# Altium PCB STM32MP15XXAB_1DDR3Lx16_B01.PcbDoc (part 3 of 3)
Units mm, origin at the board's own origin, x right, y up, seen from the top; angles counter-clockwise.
Board outline 86 x 120 mm, 4 copper layers (Top Layer, Signal Layer 1, Signal Layer 2, Bottom Layer), stack 1.571 mm thick; 144 components, 93 nets, 930 pads, 372 vias.
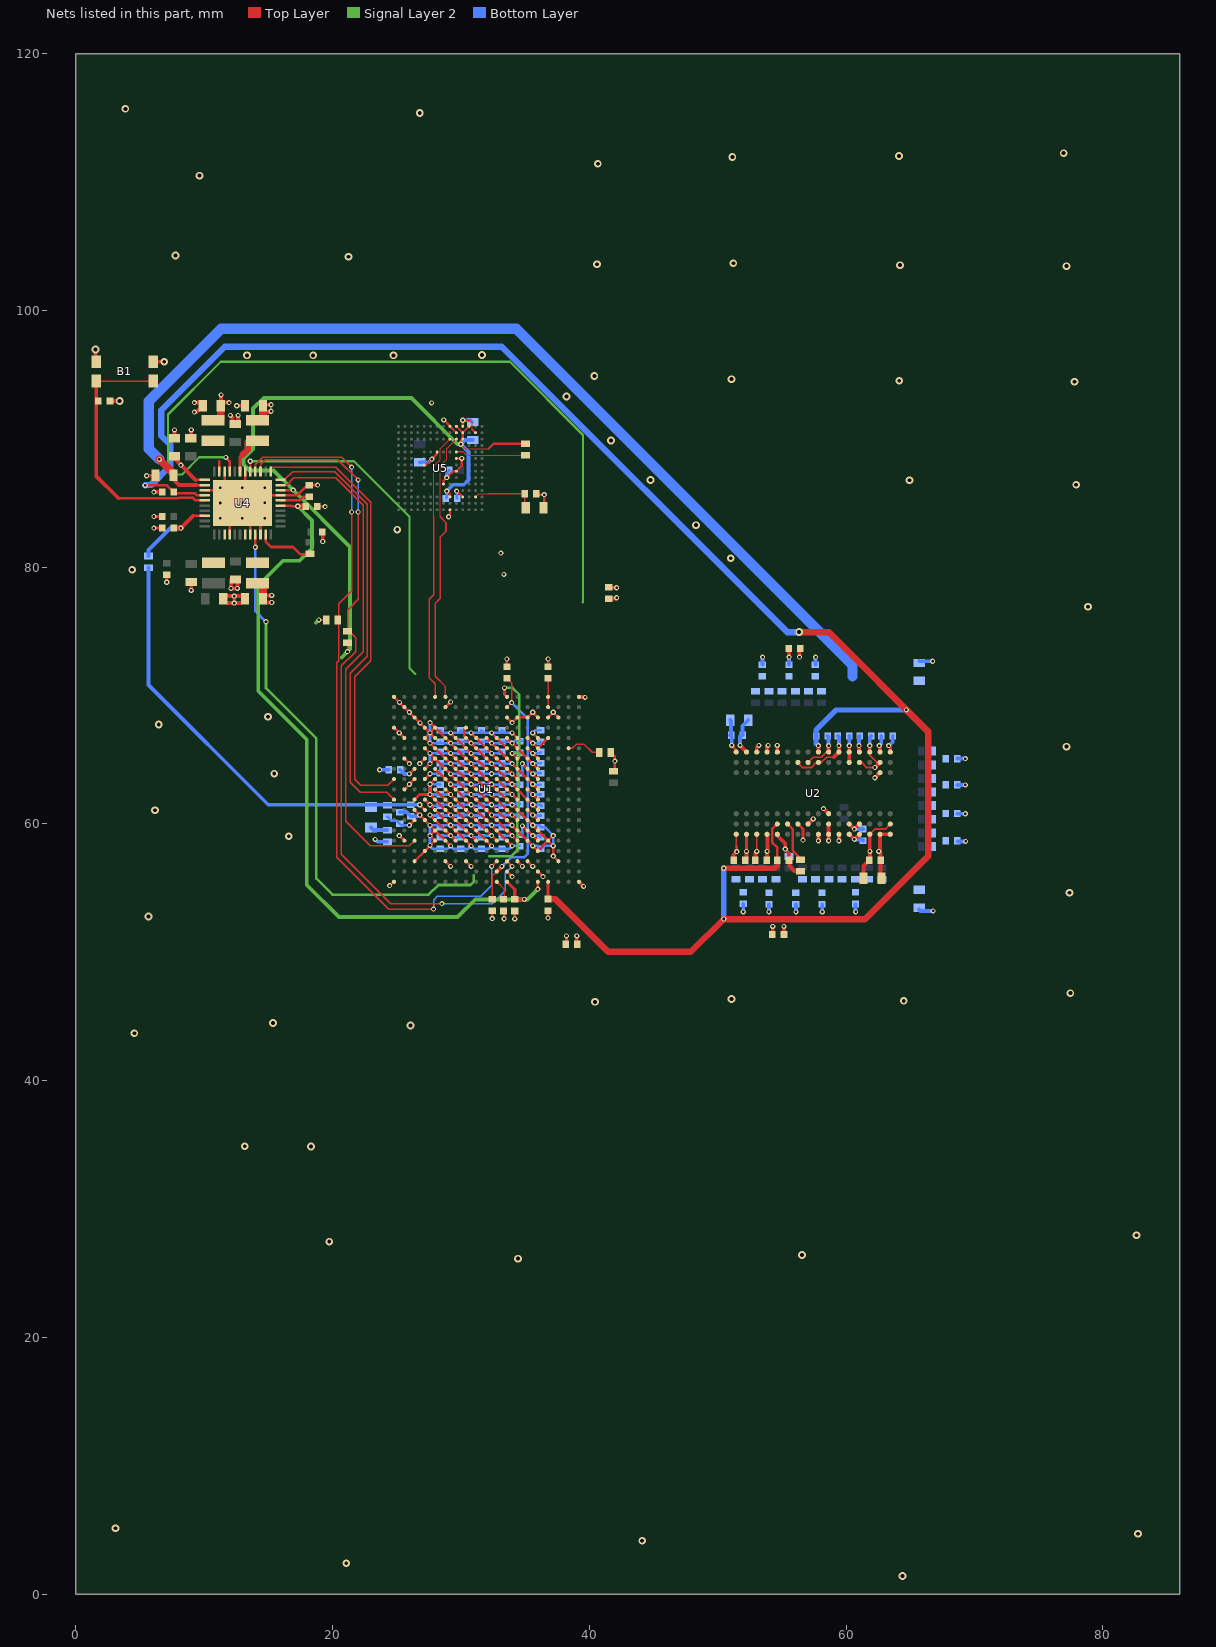
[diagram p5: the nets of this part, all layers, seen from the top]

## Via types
v1: diameter 0.4, hole 0.2, Top Layer to Bottom Layer, tented both sides, 309 vias
v2: diameter 0.6, hole 0.3, Top Layer to Bottom Layer, tented both sides, 61 vias
v3: diameter 0.4, hole 0.2, Top Layer to Signal Layer 1, tented top, 2 vias

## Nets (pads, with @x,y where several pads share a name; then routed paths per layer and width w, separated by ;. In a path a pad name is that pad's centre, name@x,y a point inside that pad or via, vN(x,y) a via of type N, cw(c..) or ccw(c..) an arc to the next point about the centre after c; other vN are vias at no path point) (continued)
GND: B1.1 B1.2 C1.1 C2.1 C3.1 C4.1 C5.1 C6.1 C7.1 C8.1 C9.1 C10.1 C11.1 C12.1 C13.1 C14.1 C15.1 C16.1 C17.1 C18.1 C19.1 C20.1 C21.1 C22.2 C23.1 C24.1 C25.1 C26.1 C27.1 C28.1 C29.1 C30.1 C31.1 C32.1 C33.1 C34.1 C35.1 C36.1 C37.1 C38.1 C39.1 C40.1 C41.1 C42.1 C43.1 C44.1 C45.1 C46.1 C47.1 C48.1 C49.1 C50.1 C51.2 C52.1 C53.1 C54.1 C55.1 C56.1 C57.1 C58.1 C59.1 C60.1 C61.1 C62.1 C63.1 C64.1 C65.1 C66.1 C67.1 C68.1 C69.1 C70.1 C71.1 C72.1 C73.1 C74.1 C75.1 C76.1 C77.1 C78.1 C79.1 C80.1 C81.1 C82.1 C83.1 C84.1 C85.1 C86.1 C87.1 C88.1 C89.1 C90.1 C91.1 C92.1 C93.1 C94.1 C95.1 C96.1 C97.1 R26.1 R27.2 R29.1 R30.1 U1.A1 U1.A19 U1.B2 U1.B6 U1.C3 U1.C12 U1.C13 U1.C14 U1.C15 U1.C16 U1.C17 U1.D1 U1.D4 U1.D5 U1.D8 U1.E2 U1.E4 U1.E5 U1.E6 U1.E8 U1.E10 U1.E12 U1.E14 U1.E16 U1.F5 U1.F7 U1.F9 U1.F11 U1.F13 U1.F15 U1.G2 U1.G4 U1.G6 U1.G8 U1.G10 U1.G12 U1.G14 U1.H5 U1.H7 U1.H9 U1.H11 U1.H13 U1.H15 U1.J3 U1.J4 U1.J6 U1.J8 U1.J10 U1.J12 U1.J14 U1.K2 U1.K5 U1.K7 U1.K9 U1.K11 U1.K13 U1.K15 U1.L4 U1.L6 U1.L8 U1.L10 U1.L12 U1.L14 U1.M3 U1.M5 U1.M7 U1.M9 U1.M11 U1.M13 U1.M15 U1.N4 U1.N6 U1.N8 U1.N10 U1.N12 U1.N14 U1.P5 U1.P7 U1.P9 U1.P11 U1.P13 U1.P15 U1.R2 U1.R5 U1.R6 U1.R8 U1.R10 U1.R12 U1.R14 U1.R16 U1.T4 U1.T15 U1.U3 U1.U6 U1.U8 U1.U13 U1.U14 U1.U17 U1.V12 U1.V15 U1.W1 U1.W19 U2.A9 U2.B1 U2.B3 U2.B9 U2.D1 U2.D8 U2.E1 U2.E2 U2.E8 U2.F9 U2.G1 U2.G8 U2.G9 U2.J2 U2.J8 U2.M1 U2.M9 U2.P1 U2.P9 U2.T1 U2.T9 U4.6 U4.10 U4.15 U4.26 U4.30 U4.32 U4.41 U4.ep U5.A6 U5.C4 U5.E7 U5.G5 U5.H10 U5.J5 U5.K8 U5.N2 U5.N5 U5.P4 U5.P6 | length 253.9
  Top Layer w0.09: 30.675,91.45 30.9,91.225 30.9,90.725
  Top Layer w0.12: U1.U17@37.55,57.1 U1.U17@37.6,57.1 ; U2.M1@54.65,65.6 U2.M1@54.65,65.7 ; C25.1@55.54,57.19 C25.1@55.56,57.17 ; v1@58.65,58.61 v1(58.65,58.7) ; U2.E8@60.25,60 U2.E8@60.27,60
  Top Layer w0.15: 51.45,58.25 U2.T9@51.45,59.2 ; v1(53.05,57.87) U2.P9@53.05,59.2 ; U2.J2@57.05,64.8 57.45,65.2 58.07,65.2 58.47,65.6 U2.G1@58.65,65.6
  Top Layer w0.175: B1.1@1.55,96.05 B1.1@1.6,96 B1.1@1.6,96.25 ; C46.1@6.2,87.125 C46.1@6.225,87.15 ; C18.1@8.975,90.05 C18.1@9,90.075 ; C29.1@9.65,92.825 C29.1@9.9,92.575 ; C40.1@11.7,77.75 C40.1@11.5,77.55 11.85,77.2 ; C33.1@12.425,91.15 C33.1@12.65,91.375 ; 12.85,77.2 C38.1@13.2,77.55 C38.1@13,77.75 ; U4.ep@13,85 13.2,85.2 13.6,85.6 U4.41@15.95,85.6 ; C52.1@18.85,84.725 v1(19.425,84.725) ; C51.2@19.2,82.75 C51.2@19.25,82.7 ; U5.H10@27.15,87.975 27.3,87.975 v1(27.75,88.425) 28.15,88.825 U5.K8@28.15,88.975 ; U5.E7@28.65,86.475 28.65,86.725 v1(28.9,86.975) 29.4,87.475 U5.G5@29.65,87.475 30.075,87.9 v1(30.075,88.475) U5.J5@29.65,88.475 ; v1(28.675,91.475) 29.15,91 U5.P6@29.15,90.975 U5.N5@29.65,90.475 ; v1(29.05,83.925) 29.15,84.025 U5.A6@29.15,84.475 ; v1(29.675,85.925) 29.7,85.925 U5.C4@30.15,85.475 ; U5.P4@30.15,90.948 U5.P4@30.15,90.975 v1(30.15,91.45) 30.675,91.45 ; 30.9,90.725 U5.N2@31.15,90.475 ; v1@33.125,81 v1(33.125,81.1) ; C82.1@35.875,85.725 35.95,85.65 v1(36.5,85.65) 36.5,84.675 C83.1@36.45,84.625
  Top Layer w0.2: U4.15@10.05,86 U4.ep@12,86 ; U4.10@11.6,87.45 11.6,86.4 U4.ep@12,86 ; U4.26@12,82.55 12,84 U4.ep@13,85 ; U4.ep@13.2,85.2 U4.6@13.2,87.45 ; U4.30@13.6,82.55 U4.ep@13.6,84.4 ; U4.32@14.4,82.55 14.4,83.6 U4.ep@13.6,84.4 ; U4.41@15.95,85.6 17.25,85.6 18.05,86.4 C43.1@18.2,86.4 ; v1(24.45,55.2) 24.75,55.5 U1.W1@24.8,55.5 ; U1.D1@24.8,67.5 U1.E2@25.6,66.7 ; U1.A1@24.8,69.9 v1(25.225,69.475) v1(26,68.7) v1(27.6,67.1) ; v1(25.2,59.1) U1.R2@25.6,58.7 ; U1.K2@25.6,62.7 v1(26,63.1) U1.J3@26.4,63.5 ; U1.G2@25.6,65.1 v1(26,64.7) ; U1.U3@26.4,57.1 U1.T4@27.2,57.9 U1.R5@28,58.7 v1(27.6,59.1) U1.P5@27.995,59.495 ; U1.M3@26.4,61.1 v1(26.8,60.7) U1.N4@27.2,60.3 27.2,60.29 v1(27.6,59.89) U1.P5@27.995,59.495 ; v1(26.8,64.7) U1.G4@27.2,65.1 ; U1.L4@27.2,61.9 v1(27.6,61.5) v1(29.2,59.9) U1.R8@30.4,58.7 v1(30.8,58.3) ; U1.J4@27.2,63.5 27.2,63.51 v1(27.6,63.91) ; v1(27.6,67.9) U1.D5@28,67.5 ; U1.P5@28,59.5 U1.P5@27.995,59.495 ; U1.K5@28,62.7 v1(29.2,61.5) U1.M7@29.6,61.1 U1.P9@31.2,59.5 U1.R10@32,58.7 v1(32.4,58.3) ; U1.H5@28,64.3 U1.J6@28.8,63.5 v1(29.2,63.1) v1(30.8,61.5) U1.M9@31.2,61.1 U1.N10@32,60.3 v1(32.4,59.9) v1(34,58.3) ; U1.E5@28,66.7 v1(27.6,67.1) ; U1.U6@28.8,57.1 v1(29.2,56.7) ; U1.B6@28.8,69.1 v1(29.2,69.5) ; v1(29.2,58.3) U1.R6@28.8,58.7 28.79,58.7 U1.P5@27.995,59.495 ; U1.U8@30.4,57.1 v1(30.8,56.7) ; U1.D8@30.4,67.5 30.27,67.37 30.27,66.83 U1.E8@30.4,66.7 v1(30.8,66.3) U1.G10@32,65.1 v1(32.4,64.7) v1(34,63.1) v1(35.6,61.5) U1.M15@36,61.1 ; U1.E10@32,66.7 v1(32.4,66.3) v1(34,64.7) U1.H13@34.4,64.3 v1(35.6,63.1) U1.K15@36,62.7 ; v1(32.45,52.63) C67.1@32.45,53.24 ; v1(33.37,52.62) C69.1@33.37,53.24 ; C66.1@33.59,72.37 v1@33.59,72.84 ; U1.V12@33.6,56.3 v1(34,55.9) ; U1.E12@33.6,66.7 v1(34,66.3) U1.G14@35.2,65.1 v1(35.6,64.7) U1.H15@36,64.3 ; U1.C12@33.6,68.3 v1(34,67.9) U1.C13@34.4,68.3 U1.C14@35.2,68.3 v1(35.6,68.7) U1.C15@36,68.3 ; v1(34.2,52.605) C71.1@34.2,53.225 ; U1.U13@34.4,57.1 v1(34.8,56.7) ; U1.U14@35.2,57.1 v1(35.6,56.7) ; U1.E14@35.2,66.7 v1(35.6,66.3) U1.F15@36,65.9 U1.E16@36.8,66.7 ; U1.V15@36,56.3 v1(36.4,55.9) ; v1(36.79,52.68) C72.1@36.79,53.26 ; U1.C16@36.8,68.3 v1(37.2,68.7) U1.C17@37.6,68.3 ; C68.1@36.8,72.25 v1(36.8,72.85) ; v1(37.2,59.1) U1.R16@36.8,58.7 ; U1.U17@37.6,57.1 v1(37.2,57.5) v1(37.2,58.3) U1.R16@36.8,58.7 ; C28.1@38.18,50.63 38.23,50.68 v1(38.23,51.28) ; R27.2@41.73,65.64 R27.2@41.67,65.58 42,65.25 v1(42,64.9) 42,64.225 R29.1@41.875,64.1 ; v1(51.1,66.12) 51.45,65.77 U2.T1@51.45,65.6 ; 51.45,58.25 51.49,58.21 v1(51.49,57.85) ; U4.ep@12,86 U4.ep@13,85 ; U4.ep@13,85 U4.ep@13.6,84.4 ; v1(27.6,67.1) U1.E4@27.2,66.7 v1(27.6,66.3) U1.F5@28,65.9 v1(29.2,64.7) U1.H7@29.6,64.3 U1.J8@30.4,63.5 v1(30.8,63.1) U1.L10@32,61.9 v1(32.4,61.5) U1.M11@32.8,61.1 v1(34,59.9) U1.R14@35.2,58.7 v1(35.6,58.3) U1.T15@36,57.9 U1.R16@36.8,58.7 ; v1(27.6,67.1) U1.D5@28,67.5 ; U1.D5@28,67.5 U1.E6@28.8,66.7 v1(29.2,66.3) U1.G8@30.4,65.1 v1(30.8,64.7) v1(32.4,63.1) U1.K11@32.8,62.7 v1(34,61.5) U1.N14@35.2,60.3 U1.P15@36,59.5 U1.R16@36.8,58.7
  Top Layer w0.25: v3(6.1,83.05) C49.1@6.75,83.05 ; v3(6.1,83.95) C41.1@6.75,83.95 ; v1(7.1,78.825) C32.1@7.1,79.4 ; v1(9,78.2) C39.1@9,78.85 ; C43.1@18.2,86.4 v1(18.85,86.4)
  Top Layer w0.3: B1.1@1.55,96.05 v2(1.55,96.95) ; C44.1@2.675,92.95 v2(3.425,92.95) ; v1(5.525,87.125) C46.1@6.2,87.125 ; B1.2@6.05,96 v2(6.9,96) ; v1(6.1,85.85) C45.1@6.75,85.85 ; C42.1@7.7,90.05 v1(7.7,90.7) ; C18.1@9,90.075 v1(9,90.7) ; v1(9.25,92.075) 9.4,92.075 C29.1@9.9,92.575 ; v1(9.25,92.825) C29.1@9.65,92.825 ; C40.1@11.7,77.75 v1(12.35,77.75) ; 11.85,77.2 v1(12.35,77.2) ; v1(12.05,91.825) 12.225,91.65 C33.1@12.225,91.375 ; C31.1@12.1,79 v1(12.1,78.35) v1(12.6,78.35) 12.6,78.9 C31.1@12.45,79.05 ; v1(12.55,92.575) C34.1@13.2,92.575 ; C33.1@12.65,91.375 v1(12.65,91.825) ; 12.85,77.2 v1(12.35,77.2) ; C38.1@13,77.75 v1(12.35,77.75) ; v1(19.25,82) C51.2@19.25,82.7 ; U1.W19@39.2,55.5 v1(39.56,55.14) ; U1.A19@39.2,69.9 39.64,69.9 v1(39.68,69.86) ; C26.1@41.52,78.45 41.57,78.4 v1(42.13,78.4) ; C73.1@51.25,57.17 51.25,57.61 v1(51.49,57.85) ; C19.1@52.94,57.17 52.94,57.76 v1(53.05,57.87) ; U2.P1@53.05,65.6 53.05,65.96 v1(53.21,66.12) ; U2.M9@54.65,59.2 54.65,59.1 55.27,58.48 v1(55.27,58.05) 55.27,58 55.54,57.73 C25.1@55.54,57.19 ; U2.M1@54.65,65.6 v1(54.65,66.12) ; v1(55.16,52.02) 55.16,51.41 C74.1@55.17,51.4 ; C27.1@55.53,73.68 55.57,73.64 v1(55.57,73) ; C25.1@55.56,57.17 55.59,57.14 55.59,56.72 55.98,56.33 R26.1@56.46,56.33 ; U2.J8@57.05,60 v1(57.45,60.4) ; v1(58.65,58.7) U2.G8@58.65,60 ; U2.G1@58.65,65.6 v1(58.65,66.1) ; v1(59.45,58.7) U2.F9@59.45,59.2 ; U2.E8@60.25,60 v1(60.65,59.6) U2.D8@61.05,60 ; U2.E2@60.25,64.8 v1(60.25,66.1) ; v1(61.01,66.1) 61.01,65.64 U2.D1@61.05,65.6 ; v1(62.25,63.6) U2.B3@62.65,64 ; v1(62.59,66.1) 62.65,66.04 U2.B1@62.65,65.6 ; C15.1@62.7,55.89 C17.1@62.7,57.17 62.7,57.72 v1(62.55,57.87) 62.65,57.97 U2.B9@62.65,59.2 U2.A9@63.45,59.2 ; v1(12.35,77.2) v1(12.35,77.75)
  Bottom Layer w0.12: v1@58.62,66.13 v1(58.65,66.1)
  Bottom Layer w0.175: v1(29.675,85.925) 29.675,85.4 C80.1@29.725,85.35 ; C81.1@30.775,91.45 C81.1@30.925,91.3
  Bottom Layer w0.2: v1(27.6,61.5) 27.68,61.42 C65.1@28.4,61.42 28.48,61.5 v1(29.2,61.5) 29.28,61.42 C88.1@30,61.42 30.08,61.5 v1(30.8,61.5) 30.88,61.42 C89.1@31.6,61.42 31.68,61.5 v1(32.4,61.5) 32.48,61.42 C90.1@33.2,61.42 33.28,61.5 v1(34,61.5) 34.06,61.56 C91.1@34.6,61.56 ; v1(27.6,63.91) 28.34,63.91 C48.1@28.4,63.97 C84.1@28.4,64.72 28.42,64.7 v1(29.2,64.7) 29.22,64.72 C35.1@30,64.72 30.02,64.7 v1(30.8,64.7) 30.82,64.72 C36.1@31.6,64.72 31.62,64.7 v1(32.4,64.7) 32.42,64.72 C37.1@33.2,64.72 33.22,64.7 v1(34,64.7) ; v1(27.6,67.9) v1(27.6,67.1) v1(27.6,66.3) 28.31,66.3 C30.1@28.4,66.39 28.49,66.3 v1(29.2,66.3) 29.91,66.3 C75.1@30,66.39 30.71,66.39 v1(30.8,66.3) 31.51,66.3 C76.1@31.6,66.39 32.31,66.39 v1(32.4,66.3) 33.11,66.3 C77.1@33.2,66.39 33.91,66.39 v1(34,66.3) 34.2,66.5 C47.1@34.8,66.5 ; v1(29.2,63.1) 29.23,63.07 C85.1@30,63.07 30.03,63.1 v1(30.8,63.1) 30.83,63.07 C86.1@31.6,63.07 31.63,63.1 v1(32.4,63.1) 32.43,63.07 C87.1@33.2,63.07 33.23,63.1 v1(34,63.1) ; v1(34,59.9) 33.34,59.9 C13.1@33.2,59.76 33.06,59.9 v1(32.4,59.9) 31.74,59.9 C94.1@31.6,59.76 31.46,59.9 v1(30.8,59.9) 30.14,59.9 C93.1@30,59.76 29.86,59.9 v1(29.2,59.9) 28.54,59.9 C92.1@28.4,59.76 28.27,59.89 v1(27.6,59.89) v1(27.6,59.1) v1(27.6,58.33) 27.6,58.25 27.78,58.07 C95.1@28.4,58.07 28.97,58.07 v1(29.2,58.3) 29.43,58.07 C96.1@30,58.07 30.57,58.07 v1(30.8,58.3) 31.03,58.07 C97.1@31.6,58.07 32.17,58.07 v1(32.4,58.3) 32.63,58.07 C14.1@33.2,58.07 33.77,58.07 v1(34,58.3) C59.1@34.6,58.3 ; v1@34.03,63.07 v1(34,63.1) ; C55.1@34.6,63.1 v1(34,63.1) ; v1(35.6,58.3) 35.99,58.3 C60.1@36.22,58.07 36.245,58.045 36.5,58.3 v1(37.2,58.3) v1(37.2,59.1) 36.54,59.76 36.27,59.76 36.13,59.9 v1(35.6,59.9) ; v1(35.6,61.5) 36.2,61.5 C57.1@36.3,61.4 ; v1(35.6,63.1) 35.63,63.07 C56.1@36.22,63.07 ; v1(35.6,64.7) 35.62,64.72 C54.1@36.22,64.72 ; v1(35.6,66.3) 36.13,66.3 C53.1@36.22,66.39 ; C12.1@51.99,53.8 C12.1@52,53.79 ; C11.1@54,53.75 C11.1@54.01,53.76 ; v1(55.27,58.05) 55.57,57.75 R30.1@55.57,57.47 ; C10.1@56.09,53.76 C10.1@56.1,53.75 ; C9.1@58.14,53.76 C9.1@58.15,53.75 ; C8.1@60.73,53.77 C8.1@60.75,53.75 ; C7.1@68.66,58.69 C7.1@68.7,58.65 ; C6.1@68.66,60.81 C6.1@68.67,60.8 ; C5.1@68.66,63.06 C5.1@68.67,63.05 ; C4.1@68.66,65.08 C4.1@68.67,65.09
  Bottom Layer w0.3: v1(23.675,64.225) C61.1@24.375,64.225 ; C50.1@25.25,60.925 25.775,60.925 C70.1@26.1,60.6 26.7,60.6 v1(26.8,60.7) ; C79.1@26.8,88.175 27.5,88.175 v1(27.75,88.425) ; v1(28.9,86.975) 28.9,87.35 C78.1@29.1,87.55 ; v1(30.15,91.45) C81.1@30.775,91.45 ; C64.1@50.95,66.91 51.1,66.76 v1(51.1,66.12) ; C16.1@50.99,68.09 51.05,68.03 C64.1@51.05,66.91 ; v1(52,53.15) C12.1@52,53.79 ; C1.1@53.48,72.4 53.5,72.42 v1(53.5,73) ; v1(54,53.15) C11.1@54,53.75 ; C2.1@55.55,72.4 55.57,72.42 v1(55.57,73) ; v1(56.1,53.15) C10.1@56.1,53.75 ; C3.1@57.61,72.4 57.63,72.42 v1(57.63,73) ; v1(58.15,53.15) C9.1@58.15,53.75 ; C24.1@58.57,66.86 58.65,66.78 v1(58.65,66.1) ; v1(60.25,66.1) 60.25,66.84 C23.1@60.27,66.86 ; v1(60.65,59.6) 60.66,59.61 C22.2@61.33,59.61 ; v1(60.75,53.15) C8.1@60.75,53.75 ; v1(61.01,66.1) 61.01,66.81 C21.1@61.06,66.86 ; v1(62.59,66.1) 62.74,66.25 C20.1@62.74,66.86 ; C63.1@65.69,53.33 65.79,53.23 v1(66.78,53.23) ; C62.1@65.71,72.7 65.73,72.68 v1(66.75,72.68) ; C6.1@68.67,60.8 v1(69.3,60.8) ; C5.1@68.67,63.05 v1(69.3,63.05) ; C4.1@68.67,65.09 v1(69.3,65.09) ; C7.1@68.7,58.65 v1(69.31,58.65)
  other v1: 25.2,67.1 26.825,67.875 33.59,72.85 33.35,79.44 11.275,83.8 12.975,83.8 14.725,83.8 11.25,85 12.975,85.025 14.725,85.025 11.275,86.2 12.975,86.2 14.725,86.2 27.725,92.8
  other v2: 64.4,1.425 21.075,2.425 44.125,4.175 82.75,4.725 3.1,5.15 34.45,26.15 56.575,26.425 19.75,27.475 82.625,27.975 18.325,34.875 13.175,34.9 4.575,43.7 26.075,44.3 15.375,44.5 40.45,46.15 64.5,46.225 51.075,46.375 77.475,46.825 5.675,52.8 77.4,54.65 16.6,59.05 6.175,61.075 15.475,63.925 77.175,66.025 6.475,67.75 14.975,68.35 78.85,76.925 4.4,79.8 51.025,80.7 25.05,82.925 48.325,83.275 77.925,86.425 64.95,86.775 44.775,86.8 41.7,89.875 38.225,93.3 77.8,94.45 64.15,94.525 51.075,94.65 40.4,94.9 13.35,96.5 18.5,96.5 24.75,96.5 31.65,96.525 77.175,103.45 64.2,103.525 40.6,103.6 51.225,103.675 21.25,104.175 7.775,104.275 9.65,110.5 40.675,111.425 51.15,111.95 64.125,112.025 76.95,112.25 26.8,115.375 3.875,115.7
I2C4_SCL: R37.2 U1.U11 U4.4 | length 56.5
  Top Layer w0.09: 13.975,87.99 13.975,87.475 U4.4@14,87.45
  Top Layer w0.1: 13.975,87.99 14.56,88.575 20.725,88.575 v1(21.5,87.8) v1@21.425,87.8 ; v1(21.5,84.3) 21.5,78.15 20.5,77.15 20.5,72.725 20.325,72.55 20.325,57.425 24.375,53.375 v1(27.875,53.375)
  Top Layer w0.2: v1(32.4,56.7) U1.U11@32.8,57.1
  Bottom Layer w0.1: v1(21.5,84.3) v1(21.5,87.8) ; v1(27.875,53.375) 27.875,54.075 28.175,54.375 31.55,54.375 32.4,55.225 v1(32.4,56.7)
I2C4_SDA: R38.2 U1.U12 U4.3 | length 56.7
  Top Layer w0.09: U4.3@14.4,87.45 14.4,88.025
  Top Layer w0.1: 14.4,88.025 14.75,88.375 20.425,88.375 v1(22,86.8) ; v1@22.025,84.275 22.025,77.5 21.175,76.65 R38.2@21.175,75 21.325,75 21.8,74.525 21.8,73.425 20.7,72.325 20.7,57.65 24.55,53.8 v1(28.525,53.8)
  Top Layer w0.2: U1.U12@33.6,57.1 v1(34,56.7)
  Bottom Layer w0.1: v1(22,84.3) v1(22,86.8) ; v1(28.525,53.8) 32.45,53.8 33.45,54.8 33.45,56.15 v1(34,56.7)
NetB1_3: B1.3 B1.4 C44.2 U4.17 | length 21.5
  Top Layer w0.1: B1.3@1.325,94.775 B1.3@1.6,94.5 B1.4@6.05,94.5
  Top Layer w0.2: 3.33,85.37 6.412,85.37 7.988,85.37 8.018,85.4 9.15,85.4 9.35,85.2 U4.17@10.05,85.2
  Top Layer w0.3: B1.3@1.6,94.45 1.6,92.95 1.6,87.1 3.33,85.37
NetC43_2: C43.2 U4.40 | length 2.4
  Top Layer w0.2: U4.40@15.95,85.2 17.45,85.2 17.75,85.5 C43.2@18.2,85.5
NetC61_2: C61.2 U1.H3 | length 1.4
  Top Layer w0.2: v1(26,63.9) U1.H3@26.4,64.3
  Bottom Layer w0.3: C61.2@25.275,64.225 25.6,63.9 v1(26,63.9)
NetC68_2: C68.2 U1.A16 U1.B16 | length 2.3
  Top Layer w0.12: U1.B16@36.8,69.1 U1.A16@36.8,69.9 C68.2@36.8,71.35
NetC69_2: C69.2 U1.W11 | length 1.6
  Top Layer w0.12: U1.W11@32.8,55.5 33.37,54.93 C69.2@33.37,54.14
NetC70_2: C70.2 L5.2 R41.1 R42.2 U1.M4 | length 34.7
  Top Layer w0.2: v1(26.8,61.5) U1.M4@27.2,61.1
  Bottom Layer w0.3: R42.2@5.675,79.975 5.675,70.825 15,61.5 C70.2@26.1,61.5 v1(26.8,61.5)
NetC82_2: C82.2 C83.2 U5.C2 | length 5.1
  Top Layer w0.09: U5.C2@31.15,85.475 31.4,85.725 32.15,85.725
  Top Layer w0.1: 32.15,85.725 C82.2@34.975,85.725 34.975,84.7 C83.2@35.05,84.625
NetL1_1: L1.1 U4.7 | length 3.2
  Top Layer w0.2: U4.7@12.8,87.45 12.8,88.55 13,88.75
  Top Layer w0.5: 13,88.75 13.4,89.15 13.4,89.75 13.5,89.85 L1.1@14,89.85
NetL2_1: L2.1 U4.11 | length 0.8
  Top Layer w0.2: U4.11@11.2,87.45 11.2,88.25
NetL3_1: L3.1 U4.29
NetL4_1: L4.1 U4.25
NetL5_1: L5.1 R39.2 | length 1.4
  Bottom Layer w0.3: L5.1@23,59.725 23.2,59.525 R39.2@24.275,59.525
NetR26_2: R26.2 U2.L8 | length 3.2
  Top Layer w0.2: U2.L8@55.45,60 55.85,59.6 55.85,57.92 56.46,57.31 R26.2@56.46,57.23
NetR27_1: R27.1 U1.F18 | length 2.8
  Top Layer w0.12: U1.F18@38.4,65.9 38.68,65.9 39,66.22 39.6,66.22 40.24,65.58 R27.1@40.77,65.58
NetR40_1: R40.1 U5.K5 | length 5.5
  Top Layer w0.09: 30.175,88.975 30.425,88.725 R40.1@35.025,88.725
  Top Layer w0.1: U5.K5@29.65,88.975 30.175,88.975
NetR43_1: R43.1 U4.33 | length 4.4
  Top Layer w0.2: U4.33@14.8,82.55 14.8,82 15.225,81.575 16.925,81.575 17.5,81 R43.1@18.25,81
NRST: U1.J1 U4.1 | length 34.8
  Top Layer w0.09: U4.1@15.2,87.45 U4.1@15.2,87.8
  Top Layer w0.1: U4.1@15.2,87.8 20.275,87.8 23,85.075 23,72.7 21.75,71.45 21.75,63.5 22.225,63.025 24.325,63.025 U1.J1@24.8,63.5
PA0_WKUP: U1.R3 U4.43 | length 39
  Top Layer w0.1: 16.45,86.4 17,86.95 20.275,86.95 22.4,84.825 22.4,73.4 21.05,72.05 21.05,60.2 22.95,58.3 26,58.3 U1.R3@26.4,58.7
  Top Layer w0.12: U4.43@15.95,86.4 16.45,86.4
PWR_ON: U1.L1 U4.44 | length 34.3
  Top Layer w0.1: U4.44@15.95,86.8 16.25,86.8 16.9,87.45 20.175,87.45 22.725,84.9 22.725,73.05 21.4,71.725 21.4,63.25 22.175,62.475 24.225,62.475 U1.L1@24.8,61.9
SDMMC2_CK: U1.A5 U5.M6 | length 20.9
  Top Layer w0.09: 27.9,83.975 27.9,87.875 28.4,88.375 28.4,89.225 U5.M6@29.15,89.975
  Top Layer w0.12: 27.9,80.825 27.9,77.85 27.55,77.5 27.55,71.375 28,70.925 U1.A5@28,69.9
  Top Layer w0.13: 27.9,80.825 27.9,83.975
SDMMC2_CMD: U1.A6 U5.M5 | length 21.5
  Top Layer w0.09: 28.4,83.925 28.4,87.9 28.9,88.4 28.9,89.225 U5.M5@29.65,89.975
  Top Layer w0.12: 28,77.175 28,71.5 28.8,70.7 U1.A6@28.8,69.9
  Top Layer w0.13: 28,77.175 28.4,77.575 28.4,82.35 28.85,82.8 28.85,83.475 28.4,83.925
VDD: C38.2 C47.2 C48.2 C65.2 C80.2 C81.2 C92.2 C93.2 C94.2 C95.2 C96.2 C97.2 L3.2 R37.1 R38.1 R39.1 R40.2 U1.A12 U1.G13 U1.J5 U1.K6 U1.L3 U1.L5 U1.L7 U1.M6 U1.M8 U1.N5 U1.N7 U1.N9 U1.P6 U1.P8 U1.P10 U1.R7 U1.R9 U1.R11 U4.31 U4.42 U5.C6 U5.M4 U5.N4 U5.P3 U5.P5 | length 152.7
  Top Layer w0.09: v1(30,89.575) 30.35,89.225 32.15,89.225
  Top Layer w0.1: v1(21.175,73.425) R38.1@21.175,74.1
  Top Layer w0.12: v1(18.95,75.9) R37.1@19.525,75.9
  Top Layer w0.175: v1(28.9,85.925) 29.15,85.675 U5.C6@29.15,85.475 ; U5.P5@29.65,90.975 U5.N4@30.15,90.475 ; v1(30,89.575) 30,89.825 U5.M4@30.15,89.975 U5.N4@30.15,90.475 ; U5.P3@30.65,90.975 U5.N4@30.15,90.475 ; 32.15,89.225 32.55,89.625 R40.2@35.025,89.625
  Top Layer w0.2: v1(14,81.55) U4.31@14,82.55 ; U4.42@15.95,86 v1(16.95,86) ; U1.L3@26.4,61.9 26.8,62.3 v1(27.6,62.3) ; v1(27.6,60.7) U1.P6@28.8,59.5 v1(29.2,59.1) U1.R7@29.6,58.7 ; U1.J5@28,63.5 v1(27.6,63.1) v1(27.6,62.3) ; U1.K6@28.8,62.7 U1.L7@29.6,61.9 U1.M8@30.4,61.1 v1(30.8,60.7) U1.N9@31.2,60.3 v1(32.4,59.1) U1.R11@32.8,58.7 ; U1.R9@31.2,58.7 v1(30.8,59.1) U1.P8@30.4,59.5 U1.N7@29.6,60.3 v1(29.2,60.7) U1.M6@28.8,61.1 v1(27.6,62.3) ; v1(33.4,70.6) 33.4,70.1 U1.A12@33.6,69.9 ; v1(34,65.5) U1.G13@34.4,65.1
  Top Layer w0.3: C38.2@14.65,77.475 14.875,77.25 v1(15.275,77.25) ; C38.2@14.85,77.8 v1(15.275,77.8)
  Top Layer w0.6: C38.2@14.6,77.55 L3.2@14.6,78.75
  Signal Layer 2 w0.2: v1(14.825,75.75) 14.825,70.575 18.75,66.65 18.75,55.75 20,54.5 27.5,54.5 28.25,55.25 30.75,55.25 31,55.5 31,56 ; 32.2,57.5 33.95,57.5 34.45,58 34.45,59.475 34.4,59.525 34.4,60.325 34.525,60.45 34.525,64.225 34.4,64.35 34.4,65.075 34.55,65.225 34.55,65.5 ; v1(33.4,70.6) 34.025,70.6 34.55,70.075 34.55,65.5 ; v1(34,65.5) 34.55,65.5
  Signal Layer 2 w0.3: 18.725,75.675 v1(18.95,75.9) ; 20.725,72.975 v1(21.175,73.425) 21.375,73.625 21.375,81.575 v1(16.95,86) 15.425,87.525 13.55,87.525 13.075,88 13.075,88.45 13.825,89.2 13.825,92.35 14.65,93.175 26.15,93.175 29.75,89.575 v1(30,89.575)
  Bottom Layer w0.1: C80.2@28.825,85.35 C80.2@28.9,85.425
  Bottom Layer w0.175: C80.2@28.9,85.425 v1(28.9,85.925)
  Bottom Layer w0.2: v1(14,81.55) 14,76.575 v1(14.825,75.75) ; v1@27.64,60.73 27.57,60.66 C92.2@28.4,60.66 29.16,60.66 v1(29.2,60.7) 29.24,60.66 C93.2@30,60.66 30.04,60.7 v1(30.8,60.7) 30.84,60.66 C94.2@31.6,60.66 ; C95.2@28.4,58.97 28.53,59.1 v1(29.2,59.1) 29.33,58.97 C96.2@30,58.97 30.13,59.1 v1(30.8,59.1) 30.93,58.97 C97.2@31.6,58.97 31.73,59.1 v1(32.4,59.1) ; C48.2@28.4,63.07 28.37,63.1 v1(27.6,63.1) v1(27.6,62.3) 28.38,62.3 C65.2@28.4,62.32 28.42,62.3 v1(29.2,62.3) ; v1(34,65.5) 34.1,65.6 C47.2@34.8,65.6
  Bottom Layer w0.25: v1(23.325,58.8) 23.5,58.625 R39.1@24.275,58.625
  Bottom Layer w0.3: v1(28.9,85.925) 29.4,86.425 30.225,86.425 30.6,86.8 30.6,88.975 v1(30,89.575) 30.325,89.9 C81.2@30.925,89.9
VDD_CORE: C13.2 C14.2 C30.2 C34.2 C35.2 C36.2 C37.2 C75.2 C76.2 C77.2 C84.2 C85.2 C86.2 C87.2 C88.2 C89.2 C90.2 C91.2 L1.2 U1.E7 U1.E9 U1.E11 U1.E13 U1.F4 U1.F6 U1.F8 U1.F10 U1.F12 U1.G5 U1.G7 U1.G9 U1.G11 U1.H4 U1.H6 U1.H8 U1.H10 U1.H12 U1.J7 U1.J9 U1.J11 U1.J13 U1.K8 U1.K10 U1.K12 U1.L9 U1.L11 U1.L13 U1.M10 U1.M12 U1.N11 U1.N13 U1.P12 U1.R13 U4.5 | length 88.2
  Top Layer w0.15: U4.5@13.6,87.45 v1(13.6,88.25)
  Top Layer w0.175: C34.2@14.6,92.575 C34.2@14.675,92.65
  Top Layer w0.2: U1.H4@27.2,64.3 v1(27.6,64.7) U1.G5@28,65.1 ; U1.F4@27.2,65.9 v1(27.6,65.5) U1.G5@28,65.1 ; U1.F6@28.8,65.9 v1(29.2,65.5) U1.G7@29.6,65.1 v1(30.8,63.9) v1(32.4,62.3) U1.L11@32.8,61.9 v1(34,60.7) U1.N13@34.4,60.3 ; v1(29.2,67.1) U1.F8@30.4,65.9 v1(30.8,65.5) U1.G9@31.2,65.1 U1.H10@32,64.3 U1.H10@32,64.25 ; v1(30.8,67.1) U1.E9@31.2,66.7 U1.F10@32,65.9 v1(32.4,65.5) U1.H12@33.6,64.3 v1(34,63.9) U1.J13@34.4,63.5 ; v1(32.4,67.1) U1.E11@32.8,66.7 U1.F12@33.6,65.9 ; U1.J11@32.8,63.5 U1.K12@33.6,62.7 v1(34,62.3) U1.L13@34.4,61.9 ; v1(34,67.1) U1.E13@34.4,66.7 ; U1.R13@34.4,58.7 v1(34,59.1) U1.P12@33.6,59.5 U1.N11@32.8,60.3 v1(32.4,60.7) U1.M10@32,61.1 U1.L9@31.2,61.9 U1.K8@30.4,62.7 U1.H6@28.8,64.3 U1.G5@28,65.1
  Top Layer w0.3: 14.6,92.1 v1@15.175,92.1 ; C34.2@14.675,92.65 v1(15.225,92.65)
  Top Layer w0.6: L1.2@14,91.45 L1.2@14.15,91.45 14.4,91.45 14.6,91.65 14.6,92.1 C34.2@14.6,92.55
  Signal Layer 2 w0.175: v1(13.6,88.25) 21.675,88.25 26,83.925 26,72.125 26.45,71.675
  Bottom Layer w0.175: v1@15.175,92.1 v1(15.225,92.15)
  Bottom Layer w0.2: v1(27.6,64.7) v1(27.6,65.5) 28.28,65.5 C84.2@28.4,65.62 28.52,65.5 v1(29.2,65.5) 29.88,65.5 C35.2@30,65.62 30.68,65.62 v1(30.8,65.5) 31.48,65.5 C36.2@31.6,65.62 32.28,65.62 v1(32.4,65.5) 33.08,65.5 C37.2@33.2,65.62 ; C30.2@28.4,67.29 28.59,67.1 v1(29.2,67.1) 29.81,67.1 C75.2@30,67.29 30.19,67.1 v1(30.8,67.1) 31.41,67.1 C76.2@31.6,67.29 31.79,67.1 v1(32.4,67.1) 33.01,67.1 C77.2@33.2,67.29 33.39,67.1 v1(34,67.1) ; v1(29.2,63.9) 29.93,63.9 C85.2@30,63.97 30.07,63.9 v1(30.8,63.9) 31.53,63.9 C86.2@31.6,63.97 31.66,63.91 v1(32.4,63.91) C87.2@33.14,63.91 ; C88.2@30,62.32 30.78,62.32 v1(30.8,62.3) 31.58,62.3 C89.2@31.6,62.32 32.38,62.32 v1(32.4,62.3) 33.18,62.3 C90.2@33.2,62.32 33.98,62.32 v1(34,62.3) ; v1(32.4,60.7) 33.16,60.7 C13.2@33.2,60.66 33.24,60.7 v1(34,60.7) C91.2@34.6,60.7 ; C14.2@33.2,58.97 33.33,59.1 v1(34,59.1) ; C87.2@33.2,63.97 C87.2@33.14,63.91 ; v1(34,63.9) 33.15,63.9 C87.2@33.14,63.91
VDD_DDR: C15.2 C16.2 C17.2 C19.2 C20.2 C21.2 C22.1 C23.2 C26.2 C27.2 C28.2 C29.2 C42.2 C53.2 C54.2 C55.2 C56.2 C57.2 C58.2 C59.2 C60.2 C64.2 C73.2 C74.2 L2.2 U1.E15 U1.F14 U1.G15 U1.H14 U1.J15 U1.K14 U1.L15 U1.M14 U1.N15 U1.P14 U1.R15 U2.A1 U2.A8 U2.B2 U2.C1 U2.C9 U2.D2 U2.D9 U2.E9 U2.F1 U2.G7 U2.H2 U2.H9 U2.K2 U2.K8 U2.N1 U2.N9 U2.R1 U2.R9 U4.9 U4.13 | length 111.2
  Top Layer w0.15: U2.K2@56.25,64.79 56.643,64.397 57.289,64.397 57.692,64.8 58.09,64.8 58.49,65.2 59.055,65.2 ; U2.D2@61.05,64.8 61.23,64.8 61.63,64.4 v1(62.25,64.4) ; U2.C9@61.85,59.2 62.25,59.6 63.05,59.6 U2.A8@63.45,60 ; U2.C1@61.85,65.6 61.85,65.35 62.4,64.8 U2.B2@62.65,64.8
  Top Layer w0.153: v1(62.25,64.4) U2.B2@62.525,64.675
  Top Layer w0.175: C42.2@7.7,88.45 C42.2@7.7,88.65 ; C29.2@11.3,92.575 11.325,92.6 C29.2@11.55,92.825
  Top Layer w0.2: 9.35,86.8 U4.13@10.05,86.8 ; v1(11.7,88.55) 12,88.25 U4.9@12,87.45 ; v1(34.8,59.85) 34.85,59.85 v1(35.6,59.1) U1.R15@36,58.7 ; v1(34.8,64.7) U1.H14@35.2,64.3 v1(35.6,63.9) U1.J15@36,63.5 ; U1.M14@35.2,61.1 v1(35.6,60.7) U1.N15@36,60.3 ; U1.K14@35.2,62.7 v1(35.6,62.3) U1.L15@36,61.9 ; U1.F14@35.2,65.9 v1(35.6,65.5) U1.G15@36,65.1 ; v1(35.6,67.1) U1.E15@36,66.7 ; v1(52.25,57.87) U2.R9@52.25,59.2 ; U2.K8@56.25,60 56.65,59.6 v1(56.65,58.75)
  Top Layer w0.3: C42.2@7.7,88.45 v1(8.2,87.95) ; v1@8.125,88.025 9.35,86.8 ; C29.2@11.325,92.6 v1(11.325,93.425) ; C29.2@11.55,92.825 v1(11.95,92.825) ; v1(39.03,51.28) 39.03,50.68 C28.2@39.08,50.63 ; C26.2@41.52,77.55 42.06,77.55 v1(42.13,77.62) ; v1(51.75,66.12) U2.R1@52.25,65.62 ; C73.2@52.25,57.27 v1(52.25,57.87) ; C19.2@53.84,57.17 53.85,57.18 v1(53.85,57.87) 53.88,57.9 53.88,59.17 U2.N9@53.85,59.2 ; U2.N1@53.85,65.6 53.85,66.04 v1(53.93,66.12) ; C74.2@54.27,51.4 54.29,51.42 v1(54.29,52.02) ; U2.K2@56.25,64.79 U2.K2@56.25,64.8 ; v1(56.38,73) 56.38,73.63 C27.2@56.43,73.68 ; v1(57.85,58.7) U2.H9@57.85,59.2 ; v1(58.25,61.2) U2.G7@58.65,60.8 ; 59.055,65.205 U2.F1@59.45,65.6 v1(59.45,66.1) ; U2.E9@60.25,59.2 v1(60.65,58.8) U2.D9@61.05,59.2 ; C15.2@61.36,55.78 61.36,56.73 C17.2@61.8,57.17 61.86,57.23 v1(61.86,57.87) 61.85,57.88 U2.C9@61.85,59.2 ; U2.C1@61.85,65.6 v1(61.85,66.1) ; v1(62.25,64.4) U2.B2@62.65,64.8 ; v1(63.32,66.1) 63.45,65.97 U2.A1@63.45,65.6
  Top Layer w0.6: L2.2@10.7,91.45 11.2,91.45 11.3,91.55 C29.2@11.3,92.55
  Signal Layer 2 w0.175: v1@11.692,88.558 9.628,88.558 8.296,87.225 7.55,87.225 7.2,87.575 7.2,91.9 11.3,96 33.825,96 39.525,90.3 39.525,77.275 39.5,77.25
  Bottom Layer w0.2: C59.2@34.6,59.15 34.8,59.35 v1(34.8,59.85) ; C55.2@34.6,63.95 34.8,64.15 v1(34.8,64.7) v1@34.888,64.7 ; v1(35.6,59.1) 36.09,59.1 C60.2@36.22,58.97 ; v1(35.6,60.7) 35.64,60.66 C58.2@36.22,60.66 ; v1(35.6,62.3) C57.2@36.22,62.3 ; v1(35.6,63.9) 35.67,63.97 C56.2@36.22,63.97 ; v1(35.6,65.5) 36.16,65.5 C54.2@36.25,65.59 ; v1(35.6,67.1) 35.79,67.29 C53.2@36.22,67.29
  Bottom Layer w0.3: v1(51.75,66.12) 51.75,66.81 C64.2@51.85,66.91 ; C64.2@51.95,66.91 51.95,67.65 C16.2@52.39,68.09 ; C23.2@59.37,66.86 59.45,66.78 v1(59.45,66.1) ; v1(60.65,58.8) 61.24,58.8 C22.1@61.33,58.71 ; v1(61.85,66.1) 61.85,66.75 C21.2@61.96,66.86 ; v1@63.35,66.1 63.64,66.39 C20.2@63.64,66.86
VDD_USB: C52.2 C71.2 U1.W12 U1.W15 U4.39 | length 58.8
  Top Layer w0.2: U4.39@15.95,84.8 16.75,84.8 16.8,84.75 v1(17.3,84.75) ; v1(36,54.934) U1.W15@36,55.5
  Top Layer w0.24: U1.W12@33.6,55.5 34.2,54.9
  Top Layer w0.3: 34.2,54.9 C71.2@34.2,54.125 v1(34.95,54.125)
  Top Layer w0.45: v1(17.3,84.75) C52.2@17.85,84.75
  Signal Layer 2 w0.3: v1(17.3,84.75) 18.4,83.65 18.4,81.475 17.428,80.503 16.153,80.503 14.225,78.575 14.225,70.35 18,66.575 18,55.25 20.5,52.75 29.75,52.75 31.125,54.125 v1(34.95,54.125) 35.191,54.125 v1(36,54.934)
VDDA: C49.2 R42.1 U4.20 | length 6.5
  Top Layer w0.2: 9.15,84 U4.20@10.05,84
  Top Layer w0.3: v1(8.2,83.05) 9.15,84
  Top Layer w0.45: C49.2@7.65,83.05 v1(8.2,83.05)
  Bottom Layer w0.3: R42.1@5.675,80.875 5.675,81.35 7.375,83.05 v1(8.2,83.05)
VDDA_1V8: C66.2 C67.2 U1.B12 U1.V11 | length 20.1
  Top Layer w0.12: C67.2@32.45,54.14 32.44,54.15 32.44,55.94 U1.V11@32.8,56.3 ; C66.2@33.59,71.35 33.96,70.98 v1(33.96,69.46) U1.B12@33.6,69.1
  Top Layer w0.3: U1.V11@32.8,56.3 v1(33.2,56.7)
  Bottom Layer w0.2: v1(33.2,56.7) 33.9,57.4 34.925,57.4 35.2,57.675 35.2,68.22 v1(33.96,69.46)
VREF+: C50.2 R41.2 U1.N3 | length 2.6
  Top Layer w0.2: v1(26,59.9) U1.N3@26.4,60.3
  Bottom Layer w0.2: R41.2@24.275,60.575 24.6,60.25 25.025,60.25 25.375,59.9 v1(26,59.9)
VREF_DDR: C24.2 C25.2 C45.2 C72.2 U1.W16 U2.H1 U2.M8 U4.16 | length 153
  Top Layer w0.2: v1(5.425,86.375) 7.125,86.375 C45.2@7.65,85.85 7.75,85.75 9.3,85.75 9.45,85.6 U4.16@10.05,85.6 ; U2.M8@54.65,60 54.25,59.6 54.25,58.57 54.66,58.16 C25.2@54.66,57.17
  Top Layer w0.24: C72.2@36.8,54.16 U1.W16@36.8,55.5
  Top Layer w0.3: U2.H1@57.85,65.6 v1(57.85,66.1)
  Top Layer w0.4: v1(50.48,56.55) 54.45,56.55 54.66,56.76 C25.2@54.66,57.17
  Top Layer w0.5: C72.2@36.8,54.16 37.35,54.16 41.47,50.04 47.92,50.04 50.47,52.59 61.48,52.59 66.39,57.5 66.39,67.21 58.65,74.95 v2(56.35,74.95)
  Bottom Layer w0.4: v1(50.48,52.6) v1(50.48,56.55) ; v1(57.85,66.1) 57.671,66.279 C24.2@57.67,66.86 57.669,67.329 59.22,68.883 v1(64.7,68.89)
  Bottom Layer w0.5: v1(5.425,86.375) 5.45,86.4 5.875,86.4 7.375,87.9 7.375,89.55 6.675,90.25 6.675,92.225 11.625,97.175 33.2,97.175 55.425,74.95 v2(56.35,74.95)
VTT_DDR: C1.2 C2.2 C3.2 C4.2 C5.2 C6.2 C7.2 C8.2 C9.2 C10.2 C11.2 C12.2 C46.2 C62.2 C63.2 R1.2 R2.2 R3.2 R4.2 R5.2 R6.2 R7.2 R8.2 R9.2 R10.2 R11.2 R12.2 R13.2 R14.2 R15.2 R16.2 R17.2 R18.2 R19.2 R20.2 R21.2 R22.2 R23.2 R24.2 R25.2 U4.14 | length 78.4
  Top Layer w0.2: 9.4,86.4 U4.14@10.05,86.4
  Top Layer w0.3: C46.2@7.625,87.3 C46.2@7.625,87.15 7.625,86.825 8.05,86.4 9.4,86.4
  Top Layer w0.6: v1(6.525,88.4) C46.2@7.625,87.3
  Bottom Layer w0.8: v1(6.525,88.4) 5.7,89.225 5.7,92.925 11.35,98.575 34.325,98.575 60.5,72.4 60.5,71.5
pads on no net: U1.A2 U1.A3 U1.A4 U1.A10 U1.A11 U1.A13 U1.A14 U1.A15 U1.B1 U1.B3 U1.B4 U1.B5 U1.B10 U1.B11 U1.B13 U1.B14 U1.B15 U1.C1 U1.C2 U1.C4 U1.C5 U1.C6 U1.C7 U1.C8 U1.C10 U1.C11 U1.D2 U1.D3 U1.D6 U1.D7 U1.D10 U1.D11 U1.D12 U1.D13 U1.D14 U1.D15 U1.D16 U1.E1 U1.E3 U1.F1 U1.F2 U1.F3 U1.G1 U1.G3 U1.H1 U1.H2 U1.J2 U1.J19 U1.K1 U1.K3 U1.K4 U1.K18 U1.L2 U1.M1 U1.M2 U1.N1 U1.N2 U1.N19 U1.P1 U1.P2 U1.P3 U1.P4 U1.R1 U1.R4 U1.T1 U1.T2 U1.T3 U1.T5 U1.T6 U1.T7 U1.T8 U1.T9 U1.T10 U1.T11 U1.T12 U1.T13 U1.T14 U1.T16 U1.U1 U1.U2 U1.U4 U1.U5 U1.U7 U1.U9 U1.U10 U1.U15 U1.U16 U1.V1 U1.V2 U1.V3 U1.V4 U1.V5 U1.V6 U1.V7 U1.V8 U1.V9 U1.V10 U1.V13 U1.V14 U1.V16 U1.V17 U1.W2 U1.W3 U1.W4 U1.W5 U1.W6 U1.W7 U1.W8 U1.W9 U1.W10 U1.W13 U1.W14 U2.J1 U2.J9 U2.L1 U2.L9 U4.2 U4.18 U4.21 U4.23 U4.34 U4.35 U4.38 U5.A1 U5.A2 U5.A7 U5.A8 U5.A9 U5.A10 U5.A11 U5.A12 U5.A13 U5.A14 U5.B1 U5.B7 U5.B8 U5.B9 U5.B10 U5.B11 U5.B12 U5.B13 U5.B14 U5.C1 U5.C3 U5.C5 U5.C7 U5.C8 U5.C9 U5.C10 U5.C11 U5.C12 U5.C13 U5.C14 U5.D1 U5.D2 U5.D3 U5.D4 U5.D12 U5.D13 U5.D14 U5.E1 U5.E2 U5.E3 U5.E5 U5.E8 U5.E9 U5.E10 U5.E12 U5.E13 U5.E14 U5.F1 U5.F2 U5.F3 U5.F10 U5.F12 U5.F13 U5.F14 U5.G1 U5.G2 U5.G3 U5.G10 U5.G12 U5.G13 U5.G14 U5.H1 U5.H2 U5.H3 U5.H5 U5.H12 U5.H13 U5.H14 U5.J1 U5.J2 U5.J3 U5.J12 U5.J13 U5.J14 U5.K1 U5.K2 U5.K3 U5.K6 U5.K7 U5.K10 U5.K12 U5.K13 U5.K14 U5.L1 U5.L2 U5.L3 U5.L12 U5.L13 U5.L14 U5.M1 U5.M2 U5.M3 U5.M7 U5.M8 U5.M9 U5.M10 U5.M11 U5.M12 U5.M13 U5.M14 U5.N1 U5.N3 U5.N6 U5.N7 U5.N8 U5.N9 U5.N10 U5.N11 U5.N12 U5.N13 U5.N14 U5.P1 U5.P2 U5.P7 U5.P8 U5.P9 U5.P10 U5.P11 U5.P12 U5.P13 U5.P14

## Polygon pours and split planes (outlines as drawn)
GND on Signal Layer 1 "GND" (solid, remove dead copper, pour order 96): 0.408,119.592 85.592,119.592 85.592,0.408 0.408,0.408
GND on Bottom Layer "L11-D_GND" (solid, remove dead copper, pour order 140): 0,-0.25 88.5,-0.25 88.5,120 0,120
VTT_DDR on Bottom Layer "VTT_DDR" (solid, pour order 98): 66.174,71.97 68.31,69.936 68.31,55.97 66.48,54.14 50.87,54.14 50.87,54.97 50.87,56.2 61.69,56.2 65.475,56.2 66.27,56.995 66.27,61.95 66.275,68.325 64.745,69.845 63.26,69.845 62.62,69.845 61.15,69.845 59.66,69.845 58.05,69.845 56.455,69.845 55.24,69.845 52.34,69.845 52.34,71.97 54.3,71.97 55.89,71.97 59.41,71.97 61.135,71.97 62.95,71.97
GND on Top Layer "GND_L01_P148" (solid, remove dead copper, pour order 148): 0.475,119.599 0.475,0.625 85.55,0.625 85.55,119.6
5V_VIN on Top Layer "5V_VIN" (solid, remove dead copper, pour order 134): 9.5,89.15 9.4,89.25 8.6,89.25 8.5,89.15 8.5,88.375 9.825,87.05 10.8,87.05 10.9,87.15 10.9,87.95 10.6,88.25 10,88.25 9.5,88.75
5V_VIN on Top Layer "5V_VIN" (solid, remove dead copper, pour order 132): 9.5,79.85 8.6,79.85 8.5,79.95 8.5,80.75 9.8,82.05 11,82.05 11.1,82.15 11.1,82.95 11.3,82.95 11.3,81.65 11.2,81.55 10.8,81.15 10,81.15 9.65,80.8 9.65,80.05
NetL4_1 on Top Layer "NetL4_1" (solid, remove dead copper, pour order 124): 11.5,81.65 11.5,82.95 11.7,82.95 11.7,80.05 11.4,79.75 9.9,79.75 9.8,79.85 9.8,80.75 10.1,81.05 10.9,81.05
NetL3_1 on Top Layer "NetL3_1" (solid, remove dead copper, pour order 122): 13.1,82.95 13.3,82.95 13.3,81.75 13.4,81.65 13.6,81.65 14.2,81.05 14.7,81.05 15.075,80.675 15.075,80.025 14.8,79.75 13.1,79.75 13.1,80.85
5V_VIN on Top Layer "NetC47_2" (solid, remove dead copper, pour order 114): 12.7,82.95 12.7,82.05 12.4,81.75 12.4,81.15 12.1,80.85 11.9,80.85 11.8,80.75 11.8,80.25 11.9,80.15 12.8,80.15 12.9,80.25 12.9,80.85 13,80.95 13,82.85 12.9,82.95
NetL2_1 on Top Layer "NetL2_1" (solid, remove dead copper, pour order 130): 11.3,88.95 11.3,88.25 11.275,88.225 11.1,88.225 10.775,88.55 10.1,88.55 9.7,88.95 9.7,90.35 9.9,90.55 11.5,90.55 11.7,90.35 11.7,89.35
5V_VIN on Top Layer "5V_VIN" (solid, remove dead copper, pour order 128): 11.9,90.05 11.8,89.95 11.8,89.05 12.1,88.75 12.4,88.75 12.9,89.25 12.9,90.05
NetL1_1 on Top Layer "NetL1_1" (solid, remove dead copper, pour order 126): 15.05,90.35 13.1,90.35 13.1,89.25 12.7,88.85 12.7,88.55 12.8,88.45 13.2,88.45 14,89.25 14.9,89.25 15.05,89.4
GND on Signal Layer 2 "L11-D_GND" (solid, remove dead copper, pour order 142): 0,120 86,120 86,-4.5 0,-4.5
VDD on Signal Layer 2 "VDD" (solid, remove dead copper, pour order 86): 14.237,78.125 20,64.367 20,55.75 32.5,55.75 32.5,59.75 31.75,59.75 31.75,60.986 30,60.986 30,63.25 23.75,63.25 23.75,68.75 17.196,78.125
5V_VIN on Signal Layer 2 "5V_VIN" (solid, pour order 136): 8.011,80.816 8,80.828 8,88.55 11.35,88.55 11.359,88.559 11.359,89.316 15.916,89.316 15.925,89.325 15.934,89.316 15.934,83.691 17.998,83.691 18.004,83.686 18,83.682 18,81.575 17.241,80.816
VDD_DDR on Signal Layer 2 "VDD_DDR" (solid, remove dead copper, pour order 81): 8.2,87.675 7.45,87.967 7.45,91.6 11.625,95.775 33.55,95.775 39,90.325 39,78.75 67.175,78.75 67.175,49.175 34.45,49.175 34.45,89.525 30.6,93.375 13.075,93.375 10.3,90.6 10.3,89.417
VDD_CORE on Signal Layer 2 "VDD_CORE" (solid, remove dead copper, pour order 88): 26.225,84.05 20.775,89.5 14.875,89.5 14.875,93 25.775,93 29.375,89.4 31.75,87.024 31.75,70.25 34.25,70.25 34.25,58.75 32.75,58.75 32.75,60 32,60 32,61.25 30.25,61.25 30.25,63.5 24.25,63.5 24.25,68.209 26.225,68.209

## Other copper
Top Layer:
  pour cut-out: 10.5,87.05 15.5,87.05 15.5,82.95 10.5,82.95
  pour cut-out: 36.55,70.225 24.425,70.225 24.425,55.225 36.55,55.225 36.55,49.325 68.525,49.325 68.525,72.747 68.497,72.775 36.55,72.775
Bottom Layer:
  pour cut-out: 36.5,55.362 41,49 52.65,49 52.65,51.875 51.625,52.9 50.45,52.9 50.48,56.625 65.475,56.625 65.675,56.625 66.275,57.116 66.275,67.068 64.825,68.375 63.854,69.25 52.3,69.25 52.3,78.15 52.3,78.9 43.074,78.9 36.5,72.326

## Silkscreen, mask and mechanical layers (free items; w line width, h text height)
Bottom Overlay:
  lines w0.2: 31.5,52.25 31.5,56.5 ; 32,56 31.5,56.5 ; 57.75,50.5 57.75,52.5 ; 58.25,52 57.75,52.5 ; 59,71.75 58.5,72.25 ; 59,72.75 58.5,72.25 ; 60.5,74 60.5,73.25 59.5,72.25 58.5,72.25 ; 70.25,61.75 69.75,62.25 ; 70.25,62.75 69.75,62.25 ; 71.25,62.25 69.75,62.25 ; 31,56 31,56 ; 31,56 31.5,56.5 ; 57.75,52.5 57.75,52.5 ; 57.75,52.5 57.25,52 57.75,52.5 ; 58.5,72.25 58.5,72.25 ; 26.25,31.75 37.75,31.75 37.75,51.25 26.25,51.25 26.25,31.75 ; 52.5,43.5 52.5,50.25 69.5,50.25 69.5,44 69.5,43.5 52.5,43.5 ; 53.75,74.25 53.75,80 63,80 63,74.25 53.75,74.25 ; 71.5,56.75 77.75,56.75 77.75,69.25 71.5,69.25 71.5,56.75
